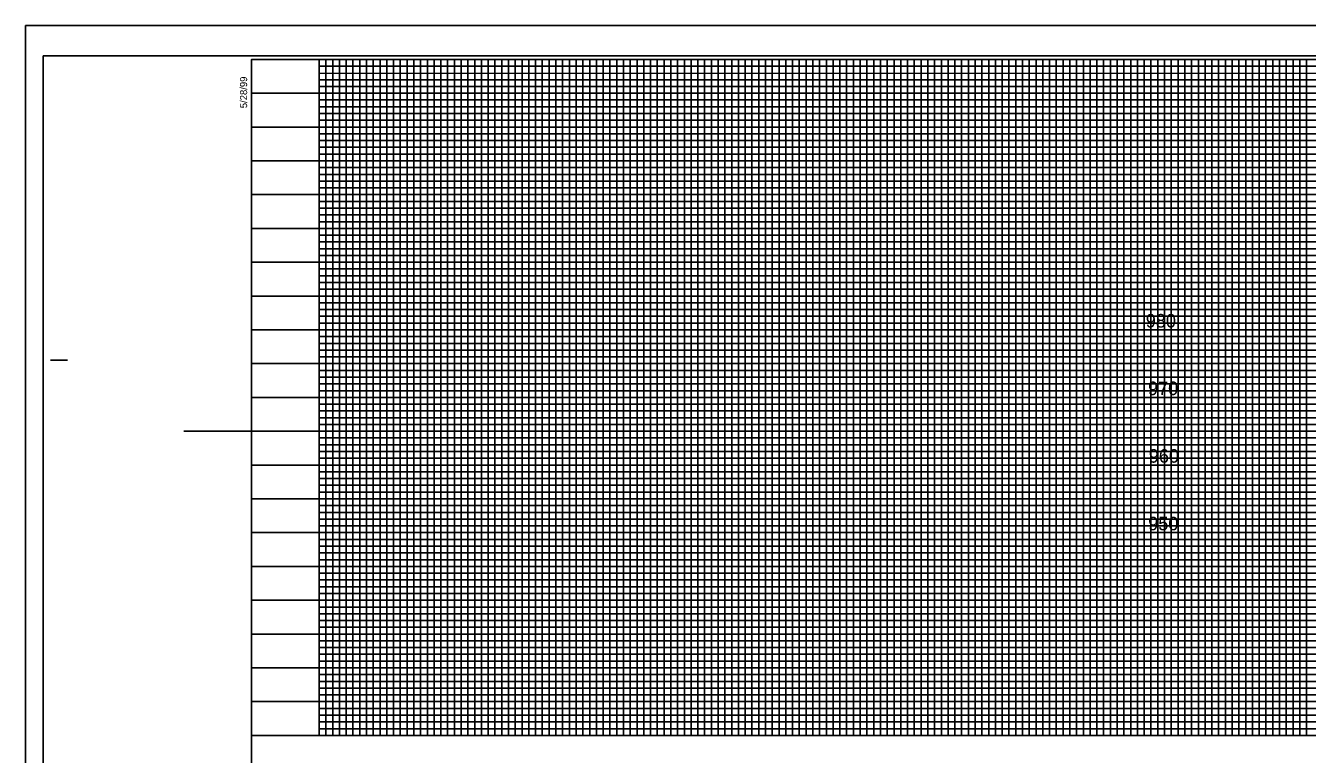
# Model space of a CAD drawing. Extents: x 1624665 to 1626605, y 896887 to 897987.
# Drawn here: x 1624665 to 1625613, y 897448 to 897987 of the extents above; entities that cross this region are included whole.
import ezdxf

# ---------------------------------------------------------------- set-up
doc = ezdxf.new("R2010")
doc.units = 0
for name, color, linetype in [('Prop DSN Text', 7, 'Continuous'), ('Prop PHM Black Shape', 7, 'Continuous'), ('Scratch_Level_6', 7, 'Continuous'), ('Sheet Cutting Line CELL', 7, 'Continuous'), ('Sheet DOT Grid CELL', 7, 'Continuous'), ('Sheet Layout Profile Border Port 1', 7, 'Continuous'), ('Sheet Plot Border Inside CELL', 7, 'Continuous'), ('Sheet Plot Border Outside CELL', 7, 'Continuous'), ('Sheet Profile CELL', 7, 'Continuous'), ('Sheet Profile Grid Major CELL', 7, 'Continuous'), ('Sheet Profile Grid Middle CELL', 7, 'Continuous'), ('Sheet Profile Grid Minor CELL', 7, 'Continuous')]:
    doc.layers.add(name, color=color, linetype=linetype)

msp = doc.modelspace()

# ---------------------------------------------------------------- linework, layer by layer
at = {"layer": 'Prop PHM Black Shape'}
for points in [[(1625482.4, 897962.44), (1625532.4, 897962.44), (1625532.4, 897937.44), (1625482.4, 897937.44)], [(1625482.4, 897937.44), (1625532.4, 897937.44), (1625532.4, 897912.44), (1625482.4, 897912.44)], [(1625122.4, 897927.44), (1625187.4, 897927.44), (1625187.4, 897897.44), (1625122.4, 897897.44)], [(1625482.4, 897912.44), (1625532.4, 897912.44), (1625532.4, 897887.44), (1625482.4, 897887.44)], [(1625482.4, 897887.44), (1625532.4, 897887.44), (1625532.4, 897862.44), (1625482.4, 897862.44)], [(1625482.4, 897862.44), (1625532.4, 897862.44), (1625532.4, 897837.44), (1625482.4, 897837.44)], [(1625482.4, 897837.44), (1625532.4, 897837.44), (1625532.4, 897812.44), (1625482.4, 897812.44)], [(1625482.4, 897812.44), (1625532.4, 897812.44), (1625532.4, 897787.44), (1625482.4, 897787.44)], [(1625482.4, 897787.44), (1625532.4, 897787.44), (1625532.4, 897762.44), (1625482.4, 897762.44)], [(1625482.4, 897762.44), (1625532.4, 897762.44), (1625532.4, 897737.44), (1625482.4, 897737.44)], [(1625482.4, 897737.44), (1625532.4, 897737.44), (1625532.4, 897712.44), (1625482.4, 897712.44)], [(1625482.4, 897712.44), (1625532.4, 897712.44), (1625532.4, 897687.44), (1625482.4, 897687.44)], [(1625482.4, 897687.44), (1625532.4, 897687.44), (1625532.4, 897662.44), (1625482.4, 897662.44)], [(1625482.4, 897662.44), (1625532.4, 897662.44), (1625532.4, 897637.44), (1625482.4, 897637.44)], [(1625482.4, 897637.44), (1625532.4, 897637.44), (1625532.4, 897612.44), (1625482.4, 897612.44)], [(1625482.4, 897612.44), (1625532.4, 897612.44), (1625532.4, 897587.44), (1625482.4, 897587.44)], [(1625482.4, 897587.44), (1625532.4, 897587.44), (1625532.4, 897562.44), (1625482.4, 897562.44)], [(1625482.4, 897562.44), (1625532.4, 897562.44), (1625532.4, 897537.44), (1625482.4, 897537.44)], [(1625482.4, 897537.44), (1625532.4, 897537.44), (1625532.4, 897512.44), (1625482.4, 897512.44)], [(1625482.4, 897512.44), (1625532.4, 897512.44), (1625532.4, 897487.44), (1625482.4, 897487.44)], [(1625482.4, 897487.44), (1625532.4, 897487.44), (1625532.4, 897462.44), (1625482.4, 897462.44)]]:
    msp.add_lwpolyline(points, close=True, dxfattribs=at)
at = {"layer": 'Scratch_Level_6'}
msp.add_lwpolyline([(1625082.4, 897912.44), (1625432.4, 897912.44), (1625432.4, 897612.44), (1625082.4, 897612.44)], close=True, dxfattribs=at)
at = {"layer": 'Sheet Cutting Line CELL'}
for p, q in [((1626349.4, 897987.44), (1624665.4, 897987.44)), ((1624665.4, 897987.44), (1624665.4, 896887.44))]:
    msp.add_line(p, q, dxfattribs=at)
at = {"layer": 'Sheet DOT Grid CELL'}
for p, q in [((1624882.4, 897462.44), (1624882.4, 897962.44)), ((1624932.4, 897462.44), (1624932.4, 897962.44)), ((1624982.4, 897462.44), (1624982.4, 897962.44)), ((1625032.4, 897462.44), (1625032.4, 897962.44)), ((1625082.4, 897462.44), (1625082.4, 897962.44)), ((1625132.4, 897462.44), (1625132.4, 897962.44)), ((1625182.4, 897462.44), (1625182.4, 897962.44)), ((1625232.4, 897462.44), (1625232.4, 897962.44)), ((1625282.4, 897462.44), (1625282.4, 897962.44)), ((1625332.4, 897462.44), (1625332.4, 897962.44)), ((1625382.4, 897462.44), (1625382.4, 897962.44)), ((1625432.4, 897462.44), (1625432.4, 897962.44)), ((1625482.4, 897462.44), (1625482.4, 897962.44)), ((1625532.4, 897462.44), (1625532.4, 897962.44)), ((1625582.4, 897462.44), (1625582.4, 897962.44)), ((1626132.35, 897912.44), (1624832.4, 897912.44)), ((1626132.35, 897862.44), (1624832.4, 897862.44)), ((1626132.4, 897812.44), (1624832.4, 897812.44)), ((1626332.4, 897762.44), (1624832.4, 897762.44)), ((1626332.4, 897712.44), (1624832.4, 897712.44)), ((1626332.4, 897662.44), (1624832.4, 897662.44)), ((1626332.4, 897612.44), (1624832.4, 897612.44)), ((1626332.4, 897562.44), (1624832.4, 897562.44)), ((1626332.4, 897512.44), (1624832.4, 897512.44))]:
    msp.add_line(p, q, dxfattribs=at)
at = {"layer": 'Sheet Layout Profile Border Port 1'}
msp.add_lwpolyline([(1624882.4, 897801.39), (1624882.4, 897462.44), (1626282.4, 897462.44), (1626282.4, 897801.39)], dxfattribs=at)
at = {"layer": 'Sheet Plot Border Inside CELL'}
msp.add_lwpolyline([(1624678.4, 896909.89), (1626344.9, 896909.89), (1626344.9, 897964.99), (1624678.4, 897964.99)], close=True, dxfattribs=at)
at = {"layer": 'Sheet Plot Border Outside CELL'}
msp.add_lwpolyline([(1624665.4, 896887.44), (1626349.4, 896887.44), (1626349.4, 897987.44), (1624665.4, 897987.44)], close=True, dxfattribs=at)
at = {"layer": 'Sheet Profile CELL'}
for p, q in [((1624683.9, 897739.94), (1624696.4, 897739.94)), ((1624832.4, 897462.44), (1626332.4, 897462.44))]:
    msp.add_line(p, q, dxfattribs=at)
msp.add_lwpolyline([(1626332.4, 897962.44), (1624832.4, 897962.44), (1624832.4, 896912.44), (1626332.4, 896912.44)], close=True, dxfattribs=at)
at = {"layer": 'Sheet Profile Grid Major CELL'}
for p, q in [((1625482.4, 897937.44), (1625532.4, 897937.44)), ((1625482.4, 897912.44), (1625532.4, 897912.44)), ((1625482.4, 897887.44), (1625532.4, 897887.44)), ((1625482.4, 897862.44), (1625532.4, 897862.44)), ((1625482.4, 897837.44), (1625532.4, 897837.44)), ((1625482.4, 897812.44), (1625532.4, 897812.44)), ((1625482.4, 897787.44), (1625532.4, 897787.44)), ((1625482.4, 897762.44), (1625532.4, 897762.44)), ((1625482.4, 897737.44), (1625532.4, 897737.44)), ((1625482.4, 897712.44), (1625532.4, 897712.44)), ((1624782.4, 897687.44), (1624832.4, 897687.44)), ((1625482.4, 897687.44), (1625532.4, 897687.44)), ((1625482.4, 897662.44), (1625532.4, 897662.44)), ((1625482.4, 897637.44), (1625532.4, 897637.44)), ((1625482.4, 897612.44), (1625532.4, 897612.44)), ((1625482.4, 897587.44), (1625532.4, 897587.44)), ((1625482.4, 897562.44), (1625532.4, 897562.44)), ((1625482.4, 897537.44), (1625532.4, 897537.44)), ((1625482.4, 897512.44), (1625532.4, 897512.44)), ((1625482.4, 897487.44), (1625532.4, 897487.44))]:
    msp.add_line(p, q, dxfattribs=at)
for points in [[(1624882.4, 897962.44), (1624882.4, 897462.44), (1624932.4, 897462.44), (1624932.4, 897962.44), (1624982.4, 897962.44), (1624982.4, 897462.44), (1625032.4, 897462.44), (1625032.4, 897962.44), (1625082.4, 897962.44), (1625082.4, 897462.44), (1625132.4, 897462.44), (1625132.4, 897962.44), (1625182.4, 897962.44), (1625182.4, 897462.44), (1625232.4, 897462.44), (1625232.4, 897962.44), (1625282.4, 897962.44), (1625282.4, 897462.44), (1625332.4, 897462.44), (1625332.4, 897962.44), (1625382.4, 897962.44), (1625382.4, 897462.44), (1625432.4, 897462.44), (1625432.4, 897962.44), (1625482.4, 897962.44), (1625482.4, 897462.44), (1625532.4, 897462.44), (1625532.4, 897962.44), (1625582.4, 897962.44), (1625582.4, 897462.44), (1625632.4, 897462.44)], [(1624832.4, 897912.44), (1626132.4, 897912.44)], [(1626132.4, 897862.44), (1624832.4, 897862.44), (1624832.4, 897812.44), (1626132.4, 897812.44)], [(1626332.4, 897762.44), (1624832.4, 897762.44), (1624832.4, 897712.44), (1626332.4, 897712.44)], [(1626332.4, 897662.44), (1624832.4, 897662.44), (1624832.4, 897612.44), (1626332.4, 897612.44)], [(1626332.4, 897562.44), (1624832.4, 897562.44), (1624832.4, 897562.44), (1624832.4, 897512.44), (1626332.4, 897512.44)]]:
    msp.add_lwpolyline(points, dxfattribs=at)
at = {"layer": 'Sheet Profile Grid Middle CELL'}
msp.add_line((1624832.4, 897937.44), (1626132.35, 897937.44), dxfattribs=at)
for points in [[(1624907.4, 897962.44), (1624907.4, 897462.44), (1624957.4, 897462.44), (1624957.4, 897962.44), (1625007.4, 897962.44), (1625007.4, 897462.44), (1625057.4, 897462.44), (1625057.4, 897962.44), (1625107.4, 897962.44), (1625107.4, 897462.44), (1625157.4, 897462.44), (1625157.4, 897962.44), (1625207.4, 897962.44), (1625207.4, 897462.44), (1625257.4, 897462.44), (1625257.4, 897962.44), (1625307.4, 897962.44), (1625307.4, 897462.44), (1625357.4, 897462.44), (1625357.4, 897962.44), (1625407.4, 897962.44), (1625407.4, 897462.44), (1625457.4, 897462.44), (1625457.4, 897462.44), (1625457.4, 897962.44), (1625507.4, 897962.44), (1625507.4, 897462.44), (1625557.4, 897462.44), (1625557.4, 897962.44), (1625607.4, 897962.44), (1625607.4, 897462.44), (1625657.4, 897462.44)], [(1626132.4, 897887.44), (1624832.4, 897887.44), (1624832.4, 897837.44), (1626132.4, 897837.44)], [(1626332.4, 897787.44), (1624832.4, 897787.44), (1624832.4, 897737.44), (1626157.4, 897737.44)], [(1626332.4, 897687.44), (1624832.4, 897687.44), (1624832.4, 897637.44), (1626332.4, 897637.44)], [(1626332.4, 897587.44), (1624832.4, 897587.44), (1624832.4, 897537.44), (1626332.4, 897537.44)], [(1626332.4, 897487.44), (1624832.4, 897487.44)]]:
    msp.add_lwpolyline(points, dxfattribs=at)
at = {"layer": 'Sheet Profile Grid Minor CELL'}
for p, q in [((1624882.4, 897957.44), (1626132.4, 897957.44)), ((1624882.4, 897952.44), (1624882.4, 897952.44)), ((1626132.4, 897952.44), (1624882.4, 897952.09)), ((1624882.4, 897947.44), (1626132.4, 897947.44)), ((1626132.35, 897827.44), (1624882.4, 897827.44)), ((1626132.4, 897822.44), (1624882.4, 897822.44)), ((1626132.4, 897817.44), (1624882.4, 897817.44)), ((1624882.4, 897807.44), (1626132.4, 897807.44)), ((1626132.4, 897802.44), (1624882.4, 897802.44)), ((1624882.4, 897797.44), (1626282.4, 897797.44)), ((1626282.4, 897777.44), (1624882.4, 897777.44)), ((1624882.4, 897772.44), (1626282.4, 897772.44)), ((1626282.4, 897752.44), (1624882.4, 897752.44)), ((1624882.4, 897747.44), (1626282.4, 897747.44)), ((1626282.4, 897727.44), (1624882.4, 897727.44)), ((1624882.4, 897722.44), (1626282.4, 897722.44)), ((1626282.4, 897717.44), (1624882.4, 897717.44)), ((1624882.4, 897707.44), (1626282.4, 897707.44)), ((1626282.4, 897702.44), (1624882.4, 897702.44)), ((1624882.4, 897697.44), (1626282.4, 897697.44)), ((1626282.4, 897692.44), (1624882.4, 897692.44)), ((1624882.4, 897682.44), (1626282.4, 897682.44)), ((1626282.4, 897677.44), (1624882.4, 897677.44)), ((1624882.4, 897672.44), (1626282.4, 897672.44)), ((1626282.4, 897667.44), (1624882.4, 897667.44)), ((1624882.4, 897657.44), (1626282.4, 897657.44)), ((1626282.4, 897652.44), (1624882.4, 897652.44)), ((1624882.4, 897647.44), (1626282.4, 897647.44)), ((1626282.4, 897642.44), (1624882.4, 897642.44)), ((1624882.4, 897632.44), (1626282.4, 897632.44)), ((1626282.4, 897627.44), (1624882.4, 897627.44)), ((1624882.4, 897622.44), (1626282.4, 897622.44)), ((1626282.4, 897617.44), (1624882.4, 897617.44)), ((1624882.4, 897607.44), (1626282.4, 897607.44)), ((1626282.4, 897602.44), (1624882.4, 897602.44)), ((1624882.4, 897597.44), (1626282.4, 897597.44)), ((1626282.4, 897592.44), (1624882.4, 897592.44)), ((1624882.4, 897582.44), (1626282.4, 897582.44)), ((1626282.4, 897577.44), (1624882.4, 897577.44)), ((1626282.4, 897572.44), (1624882.4, 897572.44)), ((1626282.4, 897567.44), (1624882.4, 897567.44)), ((1624882.4, 897557.44), (1626282.4, 897557.44)), ((1626282.4, 897552.44), (1624882.4, 897552.44)), ((1624882.4, 897547.44), (1626282.4, 897547.44)), ((1626282.4, 897542.44), (1624882.4, 897542.44)), ((1624882.4, 897532.44), (1626282.4, 897532.44)), ((1626282.4, 897527.44), (1624882.4, 897527.44)), ((1624882.4, 897522.44), (1626282.4, 897522.44)), ((1626282.4, 897517.44), (1624882.4, 897517.44)), ((1624882.4, 897507.44), (1626282.4, 897507.44)), ((1626282.4, 897502.44), (1624882.4, 897502.44)), ((1624882.4, 897497.44), (1626282.4, 897497.44)), ((1626282.4, 897492.44), (1624882.4, 897492.44)), ((1624882.4, 897482.44), (1626282.4, 897482.44)), ((1626282.4, 897477.44), (1624882.4, 897477.44)), ((1624882.4, 897472.44), (1626282.4, 897472.44))]:
    msp.add_line(p, q, dxfattribs=at)
for points in [[(1624887.4, 897962.44), (1624887.4, 897462.44), (1624892.4, 897462.44), (1624892.4, 897962.44), (1624897.4, 897962.44), (1624897.4, 897462.44), (1624902.4, 897462.44), (1624902.4, 897962.44), (1624912.4, 897962.44), (1624912.4, 897462.44), (1624917.4, 897462.44), (1624917.4, 897962.44), (1624922.4, 897962.44), (1624922.4, 897462.44), (1624927.4, 897462.44), (1624937.4, 897462.44), (1624942.4, 897462.44), (1624942.4, 897962.44), (1624947.4, 897962.44), (1624947.4, 897462.44), (1624952.4, 897462.44), (1624952.4, 897962.44), (1624962.4, 897962.44), (1624962.4, 897462.44), (1624967.4, 897462.44), (1624967.4, 897962.44), (1624972.4, 897962.44), (1624972.4, 897462.44), (1624977.4, 897462.44), (1624977.4, 897962.44), (1624987.4, 897962.44), (1624987.4, 897462.44), (1624992.4, 897462.44), (1624992.4, 897962.44), (1624997.4, 897962.44), (1624997.4, 897462.44), (1625002.4, 897462.44), (1625002.4, 897962.44), (1625012.4, 897962.44), (1625012.4, 897462.44), (1625017.4, 897462.44), (1625017.4, 897962.44), (1625022.4, 897962.44), (1625022.4, 897462.44), (1625027.4, 897462.44), (1625027.4, 897962.44), (1625037.4, 897962.44), (1625037.4, 897462.44), (1625042.4, 897462.44), (1625042.4, 897962.44), (1625047.4, 897962.44), (1625047.4, 897462.44), (1625052.4, 897462.44), (1625052.4, 897962.44), (1625062.4, 897962.44), (1625062.4, 897462.44), (1625067.4, 897462.44), (1625067.4, 897962.44), (1625072.4, 897962.44), (1625072.4, 897462.44), (1625077.4, 897462.44), (1625077.4, 897962.44), (1625087.4, 897962.44), (1625087.4, 897462.44), (1625092.4, 897462.44), (1625092.4, 897962.44), (1625097.4, 897962.44), (1625097.4, 897462.44)], [(1624927.4, 897462.44), (1624927.4, 897962.44), (1624937.4, 897962.44), (1624937.4, 897462.44)], [(1625097.4, 897462.44), (1625102.4, 897462.44), (1625102.4, 897962.44), (1625112.4, 897962.44), (1625112.4, 897462.44), (1625117.4, 897462.44), (1625117.4, 897962.44), (1625122.4, 897962.44), (1625122.4, 897462.44), (1625127.4, 897462.44), (1625127.4, 897962.44), (1625137.4, 897962.44), (1625137.4, 897462.44), (1625142.4, 897462.44), (1625142.4, 897962.44), (1625147.4, 897962.44), (1625147.4, 897462.44), (1625152.4, 897462.44), (1625152.4, 897962.44), (1625162.4, 897962.44), (1625162.4, 897462.44), (1625167.4, 897462.44), (1625167.4, 897962.44), (1625172.4, 897962.44), (1625172.4, 897462.44), (1625177.4, 897462.44), (1625177.4, 897962.44), (1625187.4, 897962.44), (1625187.4, 897462.44), (1625192.4, 897462.44), (1625192.4, 897962.44), (1625197.4, 897962.44), (1625197.4, 897462.44), (1625202.4, 897462.44), (1625202.4, 897962.44), (1625212.4, 897962.44), (1625212.4, 897462.44), (1625217.4, 897462.44), (1625217.4, 897962.44), (1625222.4, 897962.44), (1625222.4, 897462.44), (1625227.4, 897462.44), (1625227.4, 897962.44), (1625237.4, 897962.44), (1625237.4, 897462.44), (1625242.4, 897462.44), (1625242.4, 897962.44), (1625247.4, 897962.44), (1625247.4, 897462.44), (1625252.4, 897462.44), (1625252.4, 897962.44), (1625262.4, 897962.44), (1625262.4, 897462.44), (1625267.4, 897462.44), (1625267.4, 897962.44), (1625272.4, 897962.44), (1625272.4, 897462.44), (1625277.4, 897462.44), (1625277.4, 897962.44), (1625287.4, 897962.44), (1625287.4, 897462.44), (1625292.4, 897462.44), (1625292.4, 897962.44), (1625297.4, 897962.44), (1625297.4, 897462.44), (1625302.4, 897462.44), (1625302.4, 897962.44), (1625312.4, 897962.44), (1625312.4, 897462.44), (1625317.4, 897462.44), (1625317.4, 897962.44), (1625322.4, 897962.44), (1625322.4, 897462.44), (1625327.4, 897462.44), (1625327.4, 897962.44), (1625337.4, 897962.44), (1625337.4, 897462.44), (1625342.4, 897462.44), (1625342.4, 897962.44), (1625347.4, 897962.44), (1625347.4, 897462.44), (1625352.4, 897462.44), (1625352.4, 897962.44), (1625362.4, 897962.44), (1625362.4, 897462.44), (1625367.4, 897462.44), (1625367.4, 897962.44), (1625372.4, 897962.44), (1625372.4, 897462.44), (1625377.4, 897462.44), (1625377.4, 897962.44), (1625387.4, 897962.44), (1625387.4, 897462.44), (1625392.4, 897462.44), (1625392.4, 897962.44), (1625397.4, 897962.44), (1625397.4, 897462.44), (1625402.4, 897462.44), (1625402.4, 897962.44), (1625412.4, 897962.44)], [(1625412.4, 897962.44), (1625412.4, 897462.44), (1625417.4, 897462.44), (1625417.4, 897962.44), (1625422.4, 897962.44), (1625422.4, 897462.44), (1625427.4, 897462.44), (1625427.4, 897962.44), (1625437.4, 897962.44), (1625437.4, 897462.44), (1625442.4, 897462.44), (1625442.4, 897962.44), (1625447.4, 897962.44), (1625447.4, 897462.44), (1625452.4, 897462.44), (1625452.4, 897962.44), (1625462.4, 897962.44), (1625462.4, 897462.44), (1625467.4, 897462.44), (1625467.4, 897962.44), (1625472.4, 897962.44), (1625472.4, 897462.44), (1625477.4, 897462.44), (1625477.4, 897962.44), (1625487.4, 897962.44), (1625487.4, 897462.44), (1625492.4, 897462.44), (1625492.4, 897962.44), (1625497.4, 897962.44), (1625497.4, 897462.44), (1625502.4, 897462.44), (1625502.4, 897962.44), (1625512.4, 897962.44), (1625512.4, 897462.44), (1625517.4, 897462.44), (1625517.4, 897962.44), (1625522.4, 897962.44), (1625522.4, 897462.44), (1625527.4, 897462.44), (1625527.4, 897962.44), (1625537.4, 897962.44), (1625537.4, 897462.44), (1625537.4, 897462.44), (1625542.4, 897462.44), (1625542.4, 897962.44), (1625547.4, 897962.44), (1625547.4, 897462.44), (1625552.4, 897462.44), (1625552.4, 897962.44), (1625562.4, 897962.44), (1625562.4, 897462.44), (1625567.4, 897462.44), (1625567.4, 897962.44), (1625572.4, 897962.44), (1625572.4, 897462.44), (1625577.4, 897462.44), (1625577.4, 897962.44), (1625587.4, 897962.44), (1625587.4, 897462.44), (1625592.4, 897462.44), (1625592.4, 897962.44), (1625597.4, 897962.44), (1625597.4, 897462.44), (1625602.4, 897462.44), (1625602.4, 897962.44), (1625612.4, 897962.44), (1625612.4, 897462.44), (1625617.4, 897462.44)], [(1626132.4, 897942.44), (1624882.4, 897942.44), (1624882.4, 897932.44), (1626132.4, 897932.44)], [(1626132.35, 897927.44), (1624882.4, 897927.44), (1624882.4, 897922.44), (1626132.4, 897922.44)], [(1626132.4, 897917.44), (1624882.4, 897917.44), (1624882.4, 897907.44), (1626132.4, 897907.44)], [(1626132.4, 897902.44), (1624882.4, 897902.44), (1624882.4, 897897.44), (1626132.4, 897897.44)], [(1626132.4, 897892.44), (1624882.4, 897892.44), (1624882.4, 897882.44), (1626132.4, 897882.44)], [(1626132.4, 897877.44), (1624882.4, 897877.44), (1624882.4, 897872.44), (1626132.4, 897872.44)], [(1626132.4, 897867.44), (1624882.4, 897867.44), (1624882.4, 897857.44), (1626132.4, 897857.44)], [(1626132.4, 897852.34), (1624882.5, 897852.34), (1624882.5, 897847.44), (1626132.4, 897847.44)], [(1626132.4, 897842.44), (1624882.4, 897842.44), (1624882.4, 897832.44), (1626132.4, 897832.44)], [(1626282.4, 897792.44), (1624882.4, 897792.44), (1624882.4, 897782.44), (1626282.4, 897782.44)], [(1626282.4, 897767.44), (1624882.4, 897767.44), (1624882.4, 897757.44), (1626282.4, 897757.44)], [(1626282.4, 897742.44), (1624882.4, 897742.44), (1624882.4, 897732.44), (1626282.4, 897732.44)], [(1626282.4, 897467.44), (1624882.4, 897467.44)]]:
    msp.add_lwpolyline(points, dxfattribs=at)

# ---------------------------------------------------------------- texts
at = {"layer": 'Prop DSN Text'}
for s, p in [('980', (1625493.53, 897764.17)), ('970', (1625495.17, 897714.17)), ('960', (1625495.79, 897664.17)), ('950', (1625495.34, 897614.17))]:
    msp.add_text(s, height=10, dxfattribs=at).set_placement(p)
at = {"layer": 'Sheet Profile CELL'}
msp.add_text('5/28/99', height=5.25, rotation=90, dxfattribs=at).set_placement((1624829.16, 897926.35))

doc.saveas('drawing.dxf')
